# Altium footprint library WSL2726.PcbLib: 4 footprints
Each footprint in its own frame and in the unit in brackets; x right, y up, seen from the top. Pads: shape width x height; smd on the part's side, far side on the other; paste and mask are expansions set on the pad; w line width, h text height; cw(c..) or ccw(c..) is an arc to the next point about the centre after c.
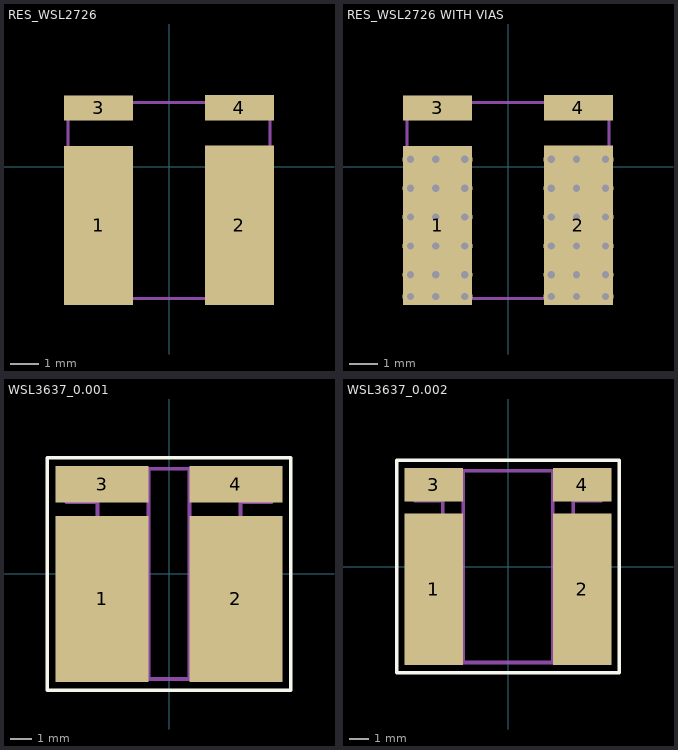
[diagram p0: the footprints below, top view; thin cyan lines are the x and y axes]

## RES_WSL2726 [mm] "Vishay Dale"
height 3.2
pads (4):
  rect 2.44x5.6 smd: 1(-2.48,-2.07) 2(2.48,-2.065)
  rect 2.44x0.89 smd: 3(-2.48,2.065) 4(2.48,2.07)
M5 Assembly Top:
  lines w0.1: -3.55,-4.65 -3.55,2.25 3.55,2.25 3.55,-4.65 -3.55,-4.65
  text ".Designator" at -1.92,-1.65 h1.02
3D body: height 3.22, standoff 0.02, extent -3.55,-4.45 3.55,2.45

## RES_WSL2726 WITH VIAS [mm] "Vishay Dale"
height 3.2
pads (4):
  rect 2.44x5.6 smd: 1(-2.48,-2.07) 2(2.48,-2.065)
  rect 2.44x0.89 smd: 3(-2.48,2.065) 4(2.48,2.07)
via -2.54,-4.572 diameter 0.559 hole 0.254
via -2.54,-3.81 diameter 0.559 hole 0.254
via -2.54,-2.794 diameter 0.559 hole 0.254
via -2.54,-1.778 diameter 0.559 hole 0.254
via -2.54,-0.762 diameter 0.559 hole 0.254
via -2.54,0.254 diameter 0.559 hole 0.254
via -1.524,-0.762 diameter 0.559 hole 0.254
via -1.524,-1.778 diameter 0.559 hole 0.254
via -1.524,-2.794 diameter 0.559 hole 0.254
via -1.524,-3.81 diameter 0.559 hole 0.254
via -1.524,-4.572 diameter 0.559 hole 0.254
via -3.429,-4.572 diameter 0.559 hole 0.254
via -3.429,-3.81 diameter 0.559 hole 0.254
via -3.429,-2.794 diameter 0.559 hole 0.254
via -3.429,-1.778 diameter 0.559 hole 0.254
via -3.429,-0.762 diameter 0.559 hole 0.254
via -3.429,0.254 diameter 0.559 hole 0.254
via -1.524,0.254 diameter 0.559 hole 0.254
via 3.429,-0.762 diameter 0.559 hole 0.254
via 1.524,-0.762 diameter 0.559 hole 0.254
via 1.524,-1.778 diameter 0.559 hole 0.254
via 1.524,-2.794 diameter 0.559 hole 0.254
via 1.524,-3.81 diameter 0.559 hole 0.254
via 1.524,-4.572 diameter 0.559 hole 0.254
via 3.429,-4.572 diameter 0.559 hole 0.254
via 3.429,-1.778 diameter 0.559 hole 0.254
via 3.429,-2.794 diameter 0.559 hole 0.254
via 3.429,-3.81 diameter 0.559 hole 0.254
via 2.413,-4.572 diameter 0.559 hole 0.254
via 2.413,-3.81 diameter 0.559 hole 0.254
via 2.413,0.254 diameter 0.559 hole 0.254
via 3.429,0.254 diameter 0.559 hole 0.254
via 2.413,-2.794 diameter 0.559 hole 0.254
via 2.413,-1.778 diameter 0.559 hole 0.254
via 2.413,-0.762 diameter 0.559 hole 0.254
via 1.524,0.254 diameter 0.559 hole 0.254
M5 Assembly Top:
  lines w0.1: -3.55,-4.65 3.55,-4.65 3.55,2.25 -3.55,2.25 -3.55,-4.65
  text ".Designator" at -1.92,-1.65 h1.02
3D body: height 3.22, standoff 0.02, extent -3.55,-4.45 3.55,2.45

## WSL3637_0.001 [mil] "Vishay WSL3637 recommended land pattern for 0.001 to 0.0019 Ohm"
height 35
pads (4):
  rect 168x300 smd: 1(-121,-45) 2(121,-45)
  rect 168x66 smd: 3(-121,162) 4(121,162)
Top Overlay:
  lines w7: -220,-210 -220,210 220,210 220,-140 220,-210 -220,-210
M5 Assembly Top:
  lines w5: -185,-190 0,-190 185,-190 185,0 185,98 129,98 129,130 185,130 185,190 0,190 -185,190 -185,130 -129,130 -129,98 -185,98 -185,0 -185,-190
  text ".Designator" at -71.85,-17.72 h40
M13 Component Bodies Top:
  lines w7: -37,-190 -37,190 ; 37,-190 37,190 ; -185,-190 -185,0 -185,98 -129,98 -129,130 -185,130 -185,190 0,190 185,190 185,130 129,130 129,98 185,98 185,0 185,-190 0,-190 -185,-190
3D body: height 35, standoff 0, extent -184.98,-189.98 -37.02,189.98
3D body: height 35, standoff 0, extent -36.98,-189.98 36.98,189.98
3D body: height 35, standoff 0, extent 37.02,-189.98 184.98,189.98

## WSL3637_0.002 [mil] "Vishay WSL3637 recommended land pattern for 0.002 to 0.01 Ohm"
height 35
pads (4):
  rect 116x300 smd: 1(-147,-45) 2(147,-45)
  rect 116x66 smd: 3(-147,162) 4(147,162)
Top Overlay:
  lines w7: -220,-210 220,-210 220,-140 220,210 -220,210 -220,-210
M5 Assembly Top:
  lines w5: -185,-190 0,-190 185,-190 185,0 185,98 129,98 129,130 185,130 185,190 0,190 -185,190 -185,130 -129,130 -129,98 -185,98 -185,0 -185,-190
  text ".Designator" at -68.9,-20.67 h40
M13 Component Bodies Top:
  lines w7: -89,-190 -89,190 ; 89,-190 89,190 ; -185,-190 -185,0 -185,98 -129,98 -129,130 -185,130 -185,190 0,190 185,190 185,130 129,130 129,98 185,98 185,0 185,-190 0,-190 -185,-190
3D body: height 35, standoff 0, extent -88.98,-189.98 88.98,189.98
3D body: height 35, standoff 0, extent -184.98,-189.98 -89.02,189.98
3D body: height 35, standoff 0, extent 89.02,-189.98 184.98,189.98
